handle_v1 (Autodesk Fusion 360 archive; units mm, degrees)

design "handle" references "VW hood"
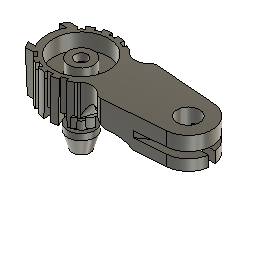
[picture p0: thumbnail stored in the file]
external_derived "ExternalDerived"
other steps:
derived_base_feature "Derived Base Feature" bodies "Body1"
named bodies: "Body1"

design "VW hood"
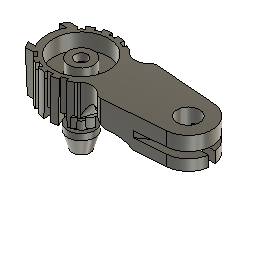
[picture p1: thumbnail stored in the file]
sketch "Sketch1" plane through (0, 0, 0) normal (0, 0, 1) x axis (1, 0, 0)
  line L1 (-15.9441, 0) -> (0, 0)
  line L2 (-10.9223, 7.05) -> (-8.3785, 7.05)
  line L3 (-10.9223, -7.05) -> (-8.3785, -7.05)
  line L4 (-11.979, 5.05) -> (-9.716, 5.05)
  line L5 (-11.979, -5.05) -> (-9.716, -5.05)
  line L6 (46.1591, 0) -> (0, 0)
  line L7 (46.1591, 7.5) -> (7.9783, 7.5)
  line L8 (46.1591, -7.5) -> (7.9783, -7.5)
  line L9 (8.8, 16.1491) -> (8.8, 0)
  line L10 (13.8, 16.1491) -> (13.8, 0)
  line L11 (46.1591, -9.25) -> (0, -9.25)
  line L12 (46.1591, 9.25) -> (0, 9.25)
  line L13 (34.4, 16.1491) -> (34.4, 0)
  line L14 (34.9982, 7.5764) -> (14.3656, 9.2053)
  line L15 (34.9982, -7.5764) -> (14.3656, -9.2053)
  line L16 (0, 4) -> (0, 0)
  line L17 (0, 10.95) -> (0, 8.8)
  line L18 (0.9, 10.913) -> (0.9, 9.9092)
  line L19 (-0.9, 10.913) -> (-0.9, 9.9092)
  line L20 (-5.0077, 9.7378) -> (-4.6236, 8.8105)
  line L21 (-3.3447, 10.4267) -> (-2.9606, 9.4993)
  line L22 (-8.353, 7.0802) -> (-7.6433, 6.3705)
  line L23 (-7.0802, 8.353) -> (-6.3705, 7.6433)
  line L24 (-10.4267, 3.3447) -> (-9.4993, 2.9606)
  line L25 (-9.7378, 5.0077) -> (-8.8105, 4.6236)
  line L26 (-10.913, -0.9) -> (-9.9092, -0.9)
  line L27 (-10.913, 0.9) -> (-9.9092, 0.9)
  line L28 (-9.7378, -5.0077) -> (-8.8105, -4.6236)
  line L29 (-10.4267, -3.3447) -> (-9.4993, -2.9606)
  line L30 (-7.0802, -8.353) -> (-6.3705, -7.6433)
  line L31 (-8.353, -7.0802) -> (-7.6433, -6.3705)
  line L32 (-3.3447, -10.4267) -> (-2.9606, -9.4993)
  line L33 (-5.0077, -9.7378) -> (-4.6236, -8.8105)
  line L34 (0.9, -10.913) -> (0.9, -9.9092)
  line L35 (-0.9, -10.913) -> (-0.9, -9.9092)
  line L36 (5.0077, -9.7378) -> (4.6236, -8.8105)
  line L37 (3.3447, -10.4267) -> (2.9606, -9.4993)
  line L38 (8.353, -7.0802) -> (7.6433, -6.3705)
  line L39 (7.0802, -8.353) -> (6.3705, -7.6433)
  line L40 (10.4267, -3.3447) -> (9.4993, -2.9606)
  line L41 (9.7378, -5.0077) -> (8.8105, -4.6236)
  line L42 (10.913, 0.9) -> (9.9092, 0.9)
  line L43 (10.913, -0.9) -> (9.9092, -0.9)
  line L44 (9.7378, 5.0077) -> (8.8105, 4.6236)
  line L45 (10.4267, 3.3447) -> (9.4993, 2.9606)
  line L46 (7.0802, 8.353) -> (6.3705, 7.6433)
  line L47 (8.353, 7.0802) -> (7.6433, 6.3705)
  line L48 (3.3447, 10.4267) -> (2.9606, 9.4993)
  line L49 (5.0077, 9.7378) -> (4.6236, 8.8105)
  line L50 (41.9277, 1.0459) -> (42, 0)
  line L51 (42, 11.6888) -> (42, 0)
  line L52 (25, 8.3658) -> (25, -8.3658)
  circle C1 centre (0, 0) radius 4
  circle C2 centre (0, 0) radius 1.5
  circle C3 centre (0, 0) radius 8.8
  circle C4 centre (0, 0) radius 10.95
  arc A1 centre (0, 0) radius 13 clockwise from (-10.9223, -7.05) to (-11.979, -5.05)
  arc A2 centre (0, 0) radius 13 clockwise from (-11.979, 5.05) to (-10.9223, 7.05)
  circle C5 centre (34.4, 0) radius 3.6
  circle C6 centre (34.4, 0) radius 7.6
  arc A3 centre (13.8, 26.3873) radius 18.8873 clockwise from (12.0677, 7.5796) to (4.2543, 10.0898)
  arc A4 centre (12.1285, 9.25) radius 1.6715 clockwise from (13.7262, 8.7588) to (11.8654, 7.5993)
  arc A5 centre (14.3319, 8.5725) radius 0.6337 clockwise from (13.7262, 8.7588) to (14.3656, 9.2053)
  arc A6 centre (13.8, -26.3873) radius 18.8873 clockwise from (4.2543, -10.0898) to (12.0677, -7.5796)
  arc A7 centre (12.1285, -9.25) radius 1.6715 clockwise from (11.8654, -7.5993) to (13.7262, -8.7588)
  arc A8 centre (14.3319, -8.5725) radius 0.6337 clockwise from (14.3656, -9.2053) to (13.7262, -8.7588)
  arc A9 centre (0, 0) radius 9.95 clockwise from (-0.9, 9.9092) to (0.9, 9.9092)
  arc A10 centre (0, 0) radius 9.95 clockwise from (-4.6236, 8.8105) to (-2.9606, 9.4993)
  arc A11 centre (0, 0) radius 9.95 clockwise from (-7.6433, 6.3705) to (-6.3705, 7.6433)
  arc A12 centre (0, 0) radius 9.95 clockwise from (-9.4993, 2.9606) to (-8.8105, 4.6236)
  arc A13 centre (0, 0) radius 9.95 clockwise from (-9.9092, -0.9) to (-9.9092, 0.9)
  arc A14 centre (0, 0) radius 9.95 clockwise from (-8.8105, -4.6236) to (-9.4993, -2.9606)
  arc A15 centre (0, 0) radius 9.95 clockwise from (-6.3705, -7.6433) to (-7.6433, -6.3705)
  arc A16 centre (0, 0) radius 9.95 clockwise from (-2.9606, -9.4993) to (-4.6236, -8.8105)
  arc A17 centre (0, 0) radius 9.95 clockwise from (0.9, -9.9092) to (-0.9, -9.9092)
  arc A18 centre (0, 0) radius 9.95 clockwise from (4.6236, -8.8105) to (2.9606, -9.4993)
  arc A19 centre (0, 0) radius 9.95 clockwise from (7.6433, -6.3705) to (6.3705, -7.6433)
  arc A20 centre (0, 0) radius 9.95 clockwise from (9.4993, -2.9606) to (8.8105, -4.6236)
  arc A21 centre (0, 0) radius 9.95 clockwise from (9.9092, 0.9) to (9.9092, -0.9)
  arc A22 centre (0, 0) radius 9.95 clockwise from (8.8105, 4.6236) to (9.4993, 2.9606)
  arc A23 centre (0, 0) radius 9.95 clockwise from (6.3705, 7.6433) to (7.6433, 6.3705)
  arc A24 centre (0, 0) radius 9.95 clockwise from (2.9606, 9.4993) to (4.6236, 8.8105)
  point P1 (0, 0)
  point P2 (0, 0)
  point P3 (0, 0)
  point P5 (0, 0)
  point P6 (0, 0)
  point P8 (-10.9223, 7.05)
  point P13 (-8.3785, 7.05)
  point P14 (-9.716, 5.05)
  point P15 (-9.716, -5.05)
  point P16 (-8.3785, -7.05)
  point P4 (0, 0)
  point P17 (0, 0)
  point P18 (7.9783, 7.5)
  point P19 (7.9783, -7.5)
  point P20 (8.8, 0)
  point P27 (34.4, 0)
  point P29 (34.4, 0)
  point P31 (34.9982, 7.5764)
  point P33 (4.2543, 10.0898)
  point P34 (11.8654, 7.5993)
  point P36 (12.0677, 7.5796)
  point P47 (34.9982, -7.5764)
  point P41 (4.2543, -10.0898)
  point P44 (11.8654, -7.5993)
  point P42 (12.0677, -7.5796)
  point P37 (14.3656, 9.2053)
  point P46 (14.3656, -9.2053)
  point P38 (13.7262, 8.7588)
  point P45 (13.7262, -8.7588)
  point P49 (0, 0)
  point P50 (0, 10.95)
  point P51 (0, 4)
  point P52 (0, 8.8)
  point P53 (-0.9, 10.913)
  point P54 (0.9, 10.913)
  point P138 (42, 0)
  point P139 (41.9277, 1.0459)
  point P141 (25, -8.3658)
  point P142 (25, 8.3658)
  coincident P1 P2
  coincident P1 P3
  concentric C2 C3
  coincident P1 P5
  coincident P1 P6
  horizontal L1
  parallel L1 L2
  coincident P8 A1
  parallel L1 L4
  parallel L1 L5
  parallel L1 L3
  concentric C3 A1
  concentric A1 A2
  coincident C4 P13
  coincident C4 P14
  coincident C4 P15
  coincident C4 P16
  coincident P4 P17
  parallel L1 L6
  coincident C4 P18
  coincident C4 P19
  coincident L6 P20
  coincident C3 P20
  tangent C3 L9
  perpendicular L7 L9
  coincident P27 P29
  concentric C5 C6
  tangent C6 L14
  coincident C6 P31
  tangent L7 A3
  coincident C4 P33
  tangent L10 A4
  coincident A3 P34
  coincident A4 P36
  tangent A4 A5
  symmetric L6 P31 P47
  symmetric L6 P33 P41
  symmetric L6 A3 A6
  symmetric L6 P34 P44
  symmetric L6 A4 A7
  symmetric L6 P36 P42
  symmetric L6 P37 P46
  symmetric L6 P38 P45
  symmetric L6 A5 A8
  coincident P5 P49
  coincident C4 P50
  vertical L16
  coincident C1 P51
  coincident C3 P52
  collinear L16 L17
  parallel L17 L19
  coincident C4 P53
  parallel L17 L18
  coincident C4 P54
  parallel L6 L12
  coincident L6 P138
  coincident C6 P138
  coincident C6 P139
  tangent C6 L51
  perpendicular L7 L51
  parallel L51 L52
  coincident L15 P141
  coincident L14 P142
  dimension "d1" diameter C1 = 8
  dimension "d2" diameter C2 = 3
  dimension "d3" diameter C3 = 17.6
  dimension "d4" diameter C4 = 21.9 (= "22 mm - 0.1 mm")
  dimension "d12" = 5
  dimension "d13" = 9.25 (= "( 18.5 / 2 ) * 1 mm")
  dimension "d15" = 25.6 (= "22 mm + ( ( 7.2 / 2 ) * 1 mm )")
  dimension "d16" diameter C5 = 7.2
  dimension "d17" diameter C6 = 15.2
  dimension "d23" distance L17 L19 = 0.9
  dimension "d24" distance L17 L18 = 0.9
  dimension "d22" C-Pattern1-Angle = 360
sketch "Sketch2" plane through (0, 0, 0) normal (0, 0, 1) x axis (1, 0, 0)
  line L1 (0, 10.95) -> (0, 8.8)
  line L2 (-3.3447, 10.4267) -> (-2.5185, 8.4319)
  line L3 (10.913, 0.9) -> (9.9092, 0.9)
  line L4 (-5.0077, 9.7378) -> (-4.1814, 7.7431)
  line L5 (-11.979, -5.05) -> (-9.716, -5.05)
  line L6 (-10.4267, 3.3447) -> (-9.4993, 2.9606)
  line L7 (-11.979, 5.05) -> (-9.716, 5.05)
  line L8 (-10.9223, -7.05) -> (-8.3785, -7.05)
  line L9 (-10.913, 0.9) -> (-9.9092, 0.9)
  line L10 (46.1591, 0) -> (0, 0)
  line L11 (-8.353, 7.0802) -> (-6.8263, 5.5535)
  line L12 (-10.9223, 7.05) -> (-8.3785, 7.05)
  line L13 (-10.4267, -3.3447) -> (-9.4993, -2.9606)
  line L14 (-8.353, -7.0802) -> (-6.8263, -5.5535)
  line L15 (-9.7378, 5.0077) -> (-8.8105, 4.6236)
  line L16 (-10.913, -0.9) -> (-9.9092, -0.9)
  line L17 (8.353, -7.0802) -> (7.6433, -6.3705)
  line L18 (7.0802, -8.353) -> (6.3705, -7.6433)
  line L19 (5.0077, -9.7378) -> (4.1814, -7.7431)
  line L20 (3.3447, -10.4267) -> (2.5185, -8.4319)
  line L21 (-3.3447, -10.4267) -> (-2.5185, -8.4319)
  line L22 (-0.9, -10.913) -> (-0.9, -8.7539)
  line L23 (0.9, -10.913) -> (0.9, -8.7539)
  line L24 (-5.0077, -9.7378) -> (-4.1814, -7.7431)
  line L25 (9.7378, -5.0077) -> (8.8105, -4.6236)
  line L26 (10.4267, -3.3447) -> (9.4993, -2.9606)
  line L27 (8.8, 16.1491) -> (8.8, 0)
  line L28 (46.1591, -9.25) -> (0, -9.25)
  line L29 (-7.0802, 8.353) -> (-5.5535, 6.8263)
  line L30 (-15.9441, 0) -> (0, 0)
  line L31 (46.1591, -7.5) -> (7.9783, -7.5)
  line L32 (-7.0802, -8.353) -> (-5.5535, -6.8263)
  line L33 (-9.7378, -5.0077) -> (-8.8105, -4.6236)
  line L34 (8.353, 7.0802) -> (7.6433, 6.3705)
  line L35 (7.0802, 8.353) -> (6.3705, 7.6433)
  line L36 (0, 4.35) -> (0, 0)
  line L37 (46.1591, 7.5) -> (7.9783, 7.5)
  line L38 (34.9982, -7.5764) -> (14.3656, -9.2053)
  line L39 (34.4, 16.1491) -> (34.4, 0)
  line L40 (34.9982, 7.5764) -> (14.3656, 9.2053)
  line L41 (13.8, 16.1491) -> (13.8, 0)
  line L42 (0.9, 10.913) -> (0.9, 8.7539)
  line L43 (9.7378, 5.0077) -> (8.8105, 4.6236)
  line L44 (-0.9, 10.913) -> (-0.9, 8.7539)
  line L45 (5.0077, 9.7378) -> (4.1814, 7.7431)
  line L46 (3.3447, 10.4267) -> (2.5185, 8.4319)
  line L47 (10.4267, 3.3447) -> (9.4993, 2.9606)
  line L48 (46.1591, 9.25) -> (0, 9.25)
  line L49 (10.913, -0.9) -> (9.9092, -0.9)
  line L50 (41.92, 1.1) -> (37.8278, 1.1)
  line L51 (41.92, -1.1) -> (37.8278, -1.1)
  line L52 (25, 8.3658) -> (25, -8.3658)
  circle C1 centre (0, 0) radius 1.5
  arc A1 centre (0, 0) radius 9.95 clockwise from (8.8105, 4.6236) to (9.4993, 2.9606)
  arc A2 centre (13.8, 26.3873) radius 18.8873 clockwise from (12.0677, 7.5796) to (4.2543, 10.0898)
  arc A3 centre (0, 0) radius 9.95 clockwise from (9.9092, 0.9) to (9.9092, -0.9)
  arc A4 centre (0, 0) radius 9.95 clockwise from (-7.6433, 6.3705) to (-6.3705, 7.6433)
  circle C2 centre (0, 0) radius 4.35
  arc A5 centre (0, 0) radius 9.95 clockwise from (-8.8105, -4.6236) to (-9.4993, -2.9606)
  arc A6 centre (0, 0) radius 13 clockwise from (-10.9223, -7.05) to (-11.979, -5.05)
  arc A7 centre (0, 0) radius 9.95 clockwise from (-6.3705, -7.6433) to (-7.6433, -6.3705)
  arc A8 centre (13.8, -26.3873) radius 18.8873 clockwise from (4.2543, -10.0898) to (12.0677, -7.5796)
  arc A9 centre (0, 0) radius 9.95 clockwise from (4.6236, -8.8105) to (2.9606, -9.4993)
  arc A10 centre (0, 0) radius 9.95 clockwise from (7.6433, -6.3705) to (6.3705, -7.6433)
  arc A11 centre (0, 0) radius 9.95 clockwise from (0.9, -9.9092) to (-0.9, -9.9092)
  arc A12 centre (0, 0) radius 9.95 clockwise from (-2.9606, -9.4993) to (-4.6236, -8.8105)
  arc A13 centre (0, 0) radius 9.95 clockwise from (9.4993, -2.9606) to (8.8105, -4.6236)
  circle C3 centre (0, 0) radius 10.95
  arc A14 centre (0, 0) radius 9.95 clockwise from (-9.4993, 2.9606) to (-8.8105, 4.6236)
  arc A15 centre (0, 0) radius 9.95 clockwise from (-9.9092, -0.9) to (-9.9092, 0.9)
  arc A16 centre (0, 0) radius 13 clockwise from (-11.979, 5.05) to (-10.9223, 7.05)
  circle C4 centre (0, 0) radius 8.8
  arc A17 centre (0, 0) radius 9.95 clockwise from (2.9606, 9.4993) to (4.6236, 8.8105)
  circle C5 centre (34.4, 0) radius 3.6
  arc A18 centre (14.3319, -8.5725) radius 0.6337 clockwise from (14.3656, -9.2053) to (13.7262, -8.7588)
  arc A19 centre (12.1285, -9.25) radius 1.6715 clockwise from (11.8654, -7.5993) to (13.7262, -8.7588)
  arc A20 centre (14.3319, 8.5725) radius 0.6337 clockwise from (13.7262, 8.7588) to (14.3656, 9.2053)
  arc A21 centre (12.1285, 9.25) radius 1.6715 clockwise from (13.7262, 8.7588) to (11.8654, 7.5993)
  circle C6 centre (34.4, 0) radius 7.6
  arc A22 centre (0, 0) radius 9.95 clockwise from (-4.6236, 8.8105) to (-2.9606, 9.4993)
  arc A23 centre (0, 0) radius 9.95 clockwise from (-0.9, 9.9092) to (0.9, 9.9092)
  arc A24 centre (0, 0) radius 9.95 clockwise from (6.3705, 7.6433) to (7.6433, 6.3705)
  circle C7 centre (0, 0) radius 2.5
  circle C8 centre (0, 0) radius 3
  point P24 (0, 0)
  point P29 (0, 0)
  point P41 (0, 0)
  point P33 (0, 0)
  point P45 (0, 0)
  point P46 (-10.9223, 7.05)
  point P42 (-8.3785, 7.05)
  point P21 (-9.716, 5.05)
  point P34 (-9.716, -5.05)
  point P39 (-8.3785, -7.05)
  point P26 (0, 0)
  point P38 (0, 0)
  point P31 (7.9783, 7.5)
  point P44 (7.9783, -7.5)
  point P40 (8.8, 0)
  point P37 (34.4, 0)
  point P48 (34.4, 0)
  point P50 (34.9982, 7.5764)
  point P53 (4.2543, 10.0898)
  point P20 (11.8654, 7.5993)
  point P52 (12.0677, 7.5796)
  point P85 (34.9982, -7.5764)
  point P61 (4.2543, -10.0898)
  point P80 (11.8654, -7.5993)
  point P49 (12.0677, -7.5796)
  point P54 (14.3656, 9.2053)
  point P81 (14.3656, -9.2053)
  point P56 (13.7262, 8.7588)
  point P84 (13.7262, -8.7588)
  point P59 (0, 0)
  point P60 (0, 10.95)
  point P107 (0, 4.35)
  point P92 (0, 8.8)
  point P103 (-0.9, 10.913)
  point P98 (0.9, 10.913)
  point P139 (0, 0)
  point P141 (41.92, 1.1)
  point P142 (41.92, -1.1)
  point P143 (37.8278, 1.1)
  point P144 (37.8278, -1.1)
  point P147 (-4.1814, 7.7431)
  point P75 (-4.6236, 8.8105)
  point P109 (-2.9606, 9.4993)
  point P148 (-6.8263, 5.5535)
  point P100 (-7.6433, 6.3705)
  point P66 (-6.3705, 7.6433)
  point P149 (-5.5535, 6.8263)
  point P150 (-2.5185, 8.4319)
  point P101 (-0.9, 9.9092)
  point P97 (0.9, 9.9092)
  point P151 (0.9, 8.7539)
  point P152 (-0.9, 8.7539)
  point P3 (2.9606, 9.4993)
  point P153 (2.5185, 8.4319)
  point P154 (4.1814, 7.7431)
  point P2 (4.6236, 8.8105)
  point P118 (2.9606, -9.4993)
  point P155 (2.5185, -8.4319)
  point P156 (4.1814, -7.7431)
  point P116 (4.6236, -8.8105)
  point P91 (0.9, -9.9092)
  point P157 (0.9, -8.7539)
  point P115 (-0.9, -9.9092)
  point P158 (-0.9, -8.7539)
  point P89 (-2.9606, -9.4993)
  point P159 (-2.5185, -8.4319)
  point P160 (-4.1814, -7.7431)
  point P65 (-4.6236, -8.8105)
  point P79 (-6.3705, -7.6433)
  point P161 (-5.5535, -6.8263)
  point P162 (-6.8263, -5.5535)
  point P83 (-7.6433, -6.3705)
  coincident P24 P29
  coincident P24 P41
  concentric C1 C4
  coincident P24 P33
  coincident P24 P45
  horizontal L30
  parallel L12 L30
  coincident P46 A6
  parallel L7 L30
  parallel L5 L30
  parallel L8 L30
  concentric A6 C4
  concentric A6 A16
  coincident P42 C3
  coincident P21 C3
  coincident P34 C3
  coincident P39 C3
  coincident P26 P38
  parallel L10 L30
  coincident P31 C3
  coincident P44 C3
  coincident P40 L10
  coincident P40 C4
  tangent L27 C4
  perpendicular L27 L37
  coincident P37 P48
  concentric C5 C6
  tangent L40 C6
  coincident P50 C6
  tangent A2 L37
  coincident P53 C3
  tangent A21 L41
  coincident P20 A2
  coincident P52 A21
  tangent A20 A21
  symmetric P50 P85 L10
  symmetric P53 P61 L10
  symmetric A2 L10 A8
  symmetric P20 P80 L10
  symmetric L10 A19 A21
  symmetric P49 P52 L10
  symmetric P54 P81 L10
  symmetric P56 P84 L10
  symmetric L10 A18 A20
  coincident P33 P59
  coincident P60 C3
  vertical L36
  coincident P107 C2
  coincident P92 C4
  collinear L1 L36
  parallel L1 L44
  coincident P103 C3
  parallel L1 L42
  coincident P98 C3
  parallel L10 L48
  coincident P24 P139
  concentric A5 C8
  coincident C6 P141
  coincident C6 P142
  coincident C5 P143
  coincident C5 P144
  coincident C4 P147
  coincident P75 L4
  coincident P109 L2
  coincident C4 P148
  coincident P100 L11
  coincident P66 L29
  coincident C4 P149
  coincident C4 P150
  coincident P101 L44
  coincident P97 L42
  coincident C4 P151
  coincident C4 P152
  coincident P3 L46
  coincident C4 P153
  coincident C4 P154
  coincident P2 L45
  coincident P118 L20
  coincident C4 P155
  coincident C4 P156
  coincident P116 L19
  coincident P91 L23
  coincident C4 P157
  coincident P115 L22
  coincident C4 P158
  coincident P89 L21
  coincident C4 P159
  coincident C4 P160
  coincident P65 L24
  coincident P79 L32
  coincident C4 P161
  coincident C4 P162
  coincident P83 L14
  dimension "d25" = 5
  dimension "d26" = 9.25 (= "( 18.5 / 2 ) * 1 mm")
  dimension "d27" = 25.6 (= "22 mm + ( ( 7.2 / 2 ) * 1 mm )")
  dimension "d30" diameter C2 = 8.7
  dimension "d31" diameter C1 = 3
  dimension "d32" diameter C4 = 17.6
  dimension "d33" diameter C3 = 21.9 (= "22 mm - 0.1 mm")
  dimension "d34" diameter C5 = 7.2
  dimension "d35" diameter C6 = 15.2
  dimension "d36" distance L1 L44 = 0.9
  dimension "d37" distance L1 L42 = 0.9
  dimension "d38" diameter C7 = 5
  dimension "d39" diameter C8 = 6
extrude "Extrude1" new body sketch "Sketch1" profile of C3 C4 A3 A6 L18 L19 A9 L20 A10 L21 L22 A11 L23 L30 A15 L31 L32 A16 L33 L34 A17 L35 L36 A18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 along normal blind 9.5
extrude "Extrude2" add sketch "Sketch1" profile of C1 C2 C3 along normal blind 4.4
extrude "Extrude3" sketch "Sketch1" profile of C1 C2 blind 4.2
extrude "Extrude4" sketch "Sketch1" profile of C5 C6 L14 L15 L52 blind -10
extrude "Extrude5" sketch "Sketch1" profile of C4 L14 A3 A4 A5 A6 A7 L15 A8 L52 blind -8
extrude "Extrude6" new body sketch "Sketch2" profile of L2 L4 A2 A4 L11 L14 A7 A8 L19 A9 L20 A11 L21 L22 L23 A12 L24 L29 C3 L32 C4 A17 A22 A23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 against normal blind 3.5
extrude "Extrude7" new body sketch "Sketch2" profile of C1 C2 C7 C8 against normal blind 7
extrude "Extrude8" sketch "Sketch2" profile of C1 C7 C8 blind -3
extrude "Extrude9" sketch "Sketch2" profile of C1 C2 C7 C8 blind -7.5 (= "-2.5 mm - 5 mm")
chamfer "Chamfer1" distance 1.5 distance 5
move "Move1"
combine "Combine1"
offset_faces "OffsetFaces1" distance -1.5
extrude "Extrude10" sketch "Sketch1" profile of C4 L2 L3 A2 L4 L5 blind -14.5
chamfer "Chamfer3" distance 1.5 distance 14.5
chamfer "Chamfer4" distance 1.5 distance 14.5
combine "Combine2"
extrude "Extrude11" cut of existing geometry blind -0.1
chamfer "Chamfer2" distance 2 distance 0.5
fillet "Fillet1" radius 10
fillet "Fillet2" radius 2
sketch "Sketch3" plane through (0, 0, 0) normal (0, 0, 1) x axis (1, 0, 0)
  line L1 (46.1591, 0) -> (0, 0)
  line L2 (34.9982, 7.5764) -> (25, 8.3658)
  line L3 (34.9982, -7.5764) -> (25, -8.3658)
  line L4 (41.9524, 0.8491) -> (42, 0)
  line L5 (41.9524, 0.8491) -> (42, 0)
  line L6 (42, 13.1287) -> (42, 0)
  line L7 (32.5, 13.1287) -> (32.5, -3.0578)
  line L8 (32.5, 3.0578) -> (25, 8.3658)
  line L9 (32.5, -3.0578) -> (25, -8.3658)
  arc A1 centre (34.4, 0) radius 7.6 clockwise from (34.9982, 7.5764) to (34.9982, -7.5764)
  arc A2 centre (34.4, 0) radius 3.6 clockwise from (32.5, 3.0578) to (32.5, -3.0578)
  point P6 (34.9982, 7.5764)
  point P7 (34.9982, -7.5764)
  point P10 (42, 0)
  point P11 (41.9524, 0.8491)
  point P15 (32.5, 3.0578)
  concentric A1 A2
  tangent L2 A1
  symmetric P6 P7 L1
  coincident L1 P10
  coincident P10 A1
  coincident P11 A1
  parallel L4 L5
  tangent L6 A1
  perpendicular L1 L6
  parallel L6 L7
  coincident L7 P15
  dimension "d78" diameter A2 = 7.2
  dimension "d79" diameter A1 = 15.2
extrude "Extrude12" sketch "Sketch3" profile of A1 A2 L2 L3 L8 L9 blind -2 from offset -4.5
extrude "Extrude13" sketch "Sketch2" profile of C5 C6 L51 L50 blind -5
extrude "Extrude14" sketch "Sketch2" profile of L2 L4 A2 A4 L11 L14 A7 A8 L19 A9 L20 A11 L21 L22 L23 A12 L24 L29 C3 L32 C4 A17 A22 A23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 blind 3
sketch "Sketch4" plane through (0, 0, 0) normal (0, 0, 1) x axis (1, 0, 0)
  line L1 (-3.3447, 10.4267) -> (-1.9022, 6.9442)
  line L2 (10.913, 0.9) -> (7.1435, 0.9)
  line L3 (8.8, 16.1491) -> (8.8, 0)
  line L4 (0, 4) -> (0, 0)
  line L5 (-10.4267, 3.3447) -> (-9.4993, 2.9606)
  line L6 (-10.4267, -3.3447) -> (-9.4993, -2.9606)
  line L7 (-9.7378, 5.0077) -> (-8.8105, 4.6236)
  line L8 (-11.979, 5.05) -> (-9.716, 5.05)
  line L9 (-8.353, 7.0802) -> (-5.6876, 4.4148)
  line L10 (-10.9223, 7.05) -> (-8.3785, 7.05)
  line L11 (-10.913, -0.9) -> (-9.9092, -0.9)
  line L12 (-7.0802, 8.353) -> (-4.4148, 5.6876)
  line L13 (-11.979, -5.05) -> (-9.716, -5.05)
  line L14 (-8.353, -7.0802) -> (-5.6876, -4.4148)
  line L15 (-10.913, 0.9) -> (-9.9092, 0.9)
  line L16 (-9.7378, -5.0077) -> (-8.8105, -4.6236)
  line L17 (-10.9223, -7.05) -> (-8.3785, -7.05)
  line L18 (-7.0802, -8.353) -> (-4.4148, -5.6876)
  line L19 (46.1591, 0) -> (0, 0)
  line L20 (46.1591, -9.25) -> (0, -9.25)
  line L21 (46.1591, -7.5) -> (7.9783, -7.5)
  line L22 (46.1591, 9.25) -> (0, 9.25)
  line L23 (-15.9441, 0) -> (0, 0)
  line L24 (0, 10.95) -> (0, 8.8)
  line L25 (-0.9, 10.913) -> (-0.9, 7.1435)
  line L26 (10.4267, 3.3447) -> (6.9442, 1.9022)
  line L27 (0.9, 10.913) -> (0.9, 7.1435)
  line L28 (8.353, 7.0802) -> (5.6876, 4.4148)
  line L29 (42, 11.6888) -> (42, 0)
  line L30 (5.0077, 9.7378) -> (3.5652, 6.2553)
  line L31 (46.1591, 7.5) -> (7.9783, 7.5)
  line L32 (9.7378, -5.0077) -> (6.2553, -3.5652)
  line L33 (0.9, -10.913) -> (0.9, -7.1435)
  line L34 (7.0802, -8.353) -> (4.4148, -5.6876)
  line L35 (8.353, -7.0802) -> (5.6876, -4.4148)
  line L36 (7.0802, 8.353) -> (4.4148, 5.6876)
  line L37 (41.9277, 1.0459) -> (42, 0)
  line L38 (34.4, 16.1491) -> (34.4, 0)
  line L39 (25, 8.3658) -> (25, -8.3658)
  line L40 (34.9982, -7.5764) -> (14.3656, -9.2053)
  line L41 (34.9982, 7.5764) -> (14.2372, 9.2155)
  line L42 (5.0077, -9.7378) -> (3.5652, -6.2553)
  line L43 (-0.9, -10.913) -> (-0.9, -7.1435)
  line L44 (-3.3447, -10.4267) -> (-1.9022, -6.9442)
  line L45 (-5.0077, -9.7378) -> (-3.5652, -6.2553)
  line L46 (3.3447, -10.4267) -> (1.9022, -6.9442)
  line L47 (10.4267, -3.3447) -> (6.9442, -1.9022)
  line L48 (10.913, -0.9) -> (7.1435, -0.9)
  line L49 (-5.0077, 9.7378) -> (-3.5652, 6.2553)
  line L50 (9.7378, 5.0077) -> (6.2553, 3.5652)
  line L51 (3.3447, 10.4267) -> (1.9022, 6.9442)
  arc A1 centre (0, 0) radius 13 clockwise from (-10.9223, -7.05) to (-11.979, -5.05)
  arc A2 centre (0, 0) radius 9.95 clockwise from (-8.8105, -4.6236) to (-9.4993, -2.9606)
  arc A3 centre (0, 0) radius 9.95 clockwise from (-9.4993, 2.9606) to (-8.8105, 4.6236)
  circle C1 centre (0, 0) radius 8.8
  arc A4 centre (13.8, -26.3873) radius 18.8873 clockwise from (4.2543, -10.0898) to (12.0677, -7.5796)
  arc A5 centre (13.8, 26.3873) radius 18.8873 clockwise from (12.0677, 7.5796) to (4.2543, 10.0898)
  circle C2 centre (0, 0) radius 10.95
  arc A6 centre (12.1285, -9.25) radius 1.6715 clockwise from (11.8654, -7.5993) to (13.7262, -8.7588)
  circle C3 centre (0, 0) radius 1.5
  circle C4 centre (34.4, 0) radius 7.6
  circle C5 centre (0, 0) radius 4
  arc A7 centre (0, 0) radius 9.95 clockwise from (-9.9092, -0.9) to (-9.9092, 0.9)
  arc A8 centre (0, 0) radius 13 clockwise from (-11.979, 5.05) to (-10.9223, 7.05)
  circle C6 centre (34.4, 0) radius 3.6
  arc A9 centre (12.1285, 9.25) radius 1.6715 clockwise from (13.7262, 8.7588) to (11.8654, 7.5993)
  arc A10 centre (14.3319, -8.5725) radius 0.6337 clockwise from (14.3656, -9.2053) to (13.7262, -8.7588)
  arc A11 centre (14.3319, 8.5725) radius 0.6337 clockwise from (13.7262, 8.7588) to (14.3656, 9.2053)
  circle C7 centre (10.333, 11.4626) radius 4.5
  circle C8 centre (10.333, -11.4626) radius 4.5
  circle C9 centre (0, 0) radius 7.2
  point P18 (0, 0)
  point P22 (0, 0)
  point P34 (0, 0)
  point P26 (0, 0)
  point P37 (0, 0)
  point P38 (-10.9223, 7.05)
  point P35 (-8.3785, 7.05)
  point P15 (-9.716, 5.05)
  point P27 (-9.716, -5.05)
  point P32 (-8.3785, -7.05)
  point P19 (0, 0)
  point P31 (0, 0)
  point P24 (7.9783, 7.5)
  point P36 (7.9783, -7.5)
  point P33 (8.8, 0)
  point P30 (34.4, 0)
  point P40 (34.4, 0)
  point P42 (34.9982, 7.5764)
  point P45 (4.2543, 10.0898)
  point P14 (11.8654, 7.5993)
  point P44 (12.0677, 7.5796)
  point P70 (34.9982, -7.5764)
  point P53 (4.2543, -10.0898)
  point P67 (11.8654, -7.5993)
  point P41 (12.0677, -7.5796)
  point P46 (14.3656, 9.2053)
  point P68 (14.3656, -9.2053)
  point P48 (13.7262, 8.7588)
  point P69 (13.7262, -8.7588)
  point P51 (0, 0)
  point P52 (0, 10.95)
  point P85 (0, 4)
  point P74 (0, 8.8)
  point P82 (-0.9, 10.913)
  point P79 (0.9, 10.913)
  point P101 (42, 0)
  point P99 (41.9277, 1.0459)
  point P102 (25, -8.3658)
  point P100 (25, 8.3658)
  point P9 (7.0802, 8.353)
  point P107 (-5.6876, 4.4148)
  point P108 (-4.4148, 5.6876)
  point P109 (-3.5652, 6.2553)
  point P110 (-0.9, 7.1435)
  point P111 (0.9, 7.1435)
  point P112 (1.9022, 6.9442)
  point P113 (3.5652, 6.2553)
  point P114 (4.4148, 5.6876)
  point P115 (5.6876, 4.4148)
  point P116 (6.2553, 3.5652)
  point P117 (6.9442, 1.9022)
  point P118 (7.1435, 0.9)
  point P119 (7.1435, -0.9)
  point P120 (6.9442, -1.9022)
  point P121 (6.2553, -3.5652)
  point P122 (5.6876, -4.4148)
  point P123 (4.4148, -5.6876)
  point P124 (3.5652, -6.2553)
  point P125 (1.9022, -6.9442)
  point P126 (0.9, -7.1435)
  point P127 (-0.9, -7.1435)
  point P128 (-1.9022, -6.9442)
  point P129 (-3.5652, -6.2553)
  point P130 (-4.4148, -5.6876)
  point P131 (-5.6876, -4.4148)
  point P132 (-1.9022, 6.9442)
  coincident P18 P22
  coincident P18 P34
  concentric C1 C3
  coincident P18 P26
  coincident P18 P37
  horizontal L23
  parallel L10 L23
  coincident P38 A1
  parallel L8 L23
  parallel L13 L23
  parallel L17 L23
  concentric A1 C1
  concentric A1 A8
  coincident P35 C2
  coincident P15 C2
  coincident P27 C2
  coincident P32 C2
  coincident P19 P31
  parallel L19 L23
  coincident P24 C2
  coincident P36 C2
  coincident P33 L19
  coincident P33 C1
  tangent L3 C1
  perpendicular L3 L31
  coincident P30 P40
  concentric C4 C6
  tangent C4 L41
  coincident P42 C4
  tangent A5 L31
  coincident P45 C2
  coincident P14 A5
  coincident P44 A9
  tangent A9 A11
  symmetric P42 P70 L19
  symmetric P45 P53 L19
  symmetric L19 A4 A5
  symmetric P14 P67 L19
  symmetric L19 A6 A9
  symmetric P41 P44 L19
  symmetric P46 P68 L19
  symmetric P48 P69 L19
  symmetric L19 A10 A11
  coincident P26 P51
  coincident P52 C2
  vertical L4
  coincident P85 C5
  coincident P74 C1
  collinear L4 L24
  parallel L24 L25
  coincident P82 C2
  parallel L24 L27
  coincident P79 C2
  parallel L19 L22
  coincident P101 L19
  coincident P101 C4
  coincident P99 C4
  tangent L29 C4
  perpendicular L29 L31
  parallel L29 L39
  coincident P102 L40
  coincident P100 L41
  coincident P46 L41
  coincident P9 C7
  symmetric L19 C7 C8
  concentric C2 C9
  coincident C9 P107
  coincident C9 P108
  coincident C9 P109
  coincident C9 P110
  coincident C9 P111
  coincident C9 P112
  coincident C9 P113
  coincident C9 P114
  coincident C9 P115
  coincident C9 P116
  coincident C9 P117
  coincident C9 P118
  coincident C9 P119
  coincident C9 P120
  coincident C9 P121
  coincident C9 P122
  coincident C9 P123
  coincident C9 P124
  coincident C9 P125
  coincident C9 P126
  coincident C9 P127
  coincident C9 P128
  coincident C9 P129
  coincident C9 P130
  coincident C9 P131
  coincident C9 P132
  dimension "d98" = 5
  dimension "d99" = 9.25 (= "( 18.5 / 2 ) * 1 mm")
  dimension "d100" = 25.6 (= "22 mm + ( ( 7.2 / 2 ) * 1 mm )")
  dimension "d103" diameter C5 = 8
  dimension "d104" diameter C3 = 3
  dimension "d105" diameter C1 = 17.6
  dimension "d106" diameter C2 = 21.9 (= "22 mm - 0.1 mm")
  dimension "d107" diameter C6 = 7.2
  dimension "d108" diameter C4 = 15.2
  dimension "d109" distance L24 L25 = 0.9
  dimension "d110" distance L24 L27 = 0.9
  dimension "d114" diameter C7 = 9
  dimension "d122" diameter C2 = 21.9
  dimension "d133" diameter C9 = 14.4
extrude "Extrude16" cut sketch "Sketch4" profile of C2 C7 C8 distance 20
extrude "Extrude18" sketch "Sketch4" profile of L2 C1 C2 L26 L28 L32 L34 L35 L36 L42 L46 L47 L48 L50 C7 C8 blind 3
extrude "Extrude21" sketch "Sketch4" profile of L1 L2 L9 L12 L14 L18 C1 L25 L26 L27 L28 L30 L32 L33 L34 L35 L36 L42 L43 L44 L45 L46 L47 L48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 blind -2
extrude "Extrude22" sketch "Sketch4" profile of L1 L2 L9 L12 L14 L18 C1 L25 L26 L27 L28 L30 L32 L33 L34 L35 L36 L42 L43 L44 L45 L46 L47 L48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 blind -3
chamfer "Chamfer6" distance 0.2 distance 11
chamfer "Chamfer7" distance 0.2 distance 3
fillet "Fillet3" radius 2
fillet "Fillet4" radius 2
fillet "Fillet5" radius 3
offset_faces "OffsetFaces2" distance 1
offset_faces "OffsetFaces3" distance 1
extrude "Extrude19" cut of existing geometry blind -0.5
